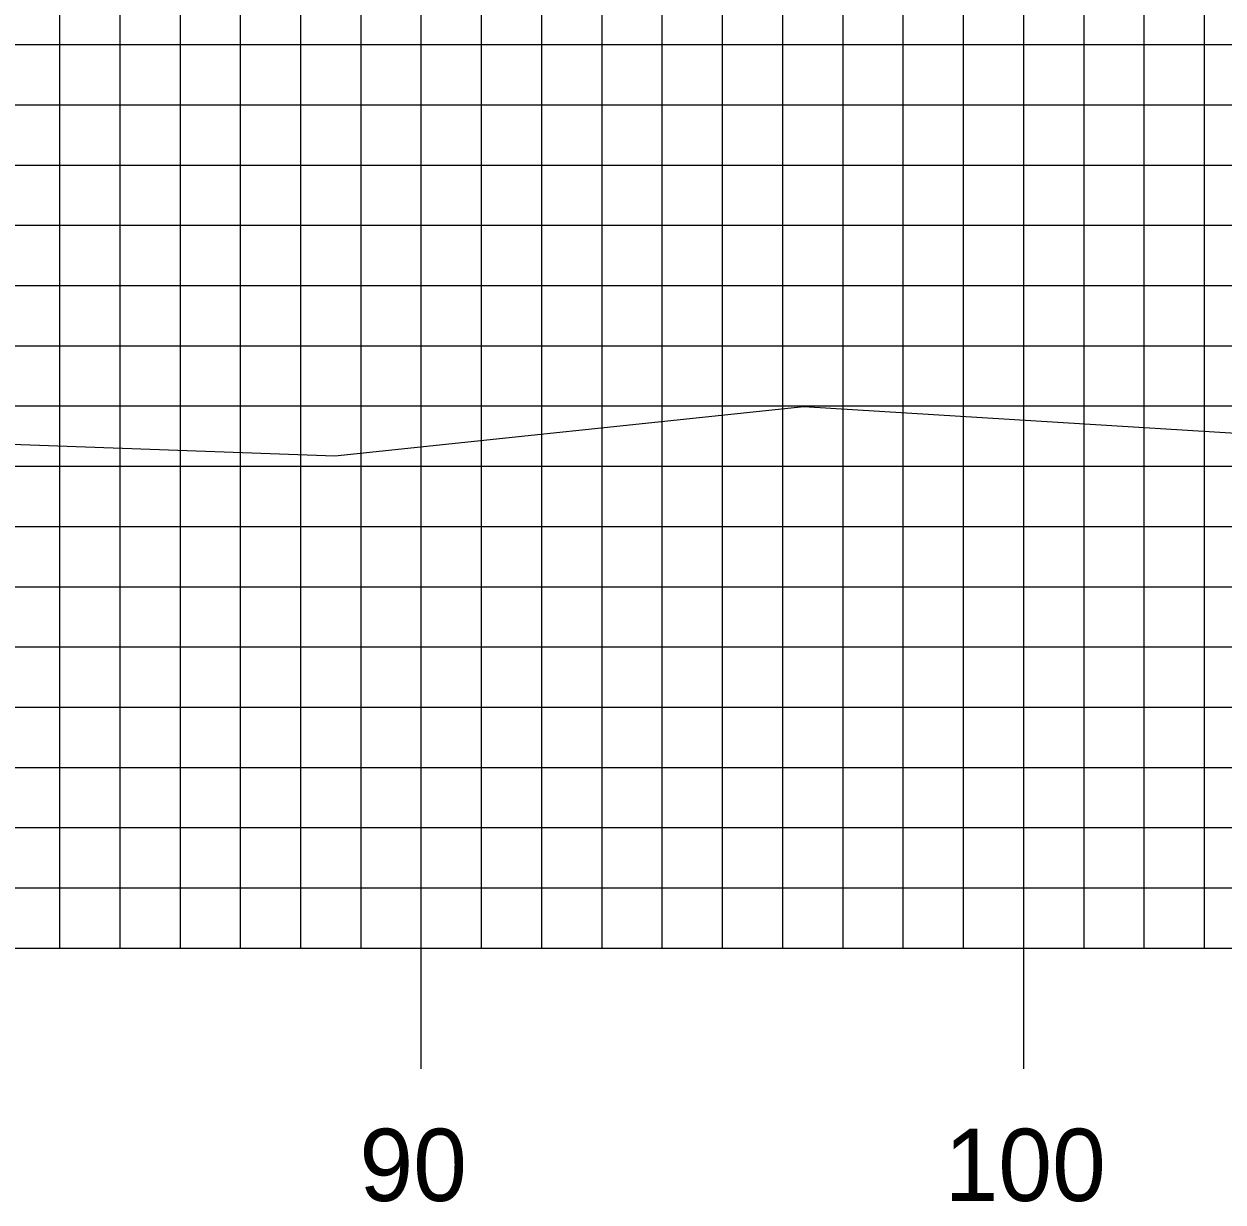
# Model space of a CAD drawing. Extents: x 1774777 to 1775120, y 442591 to 442811.
# Drawn here: x 1775026.09 to 1775045.99, y 442644.45 to 442664.01 of the extents above; entities that cross this region are included whole.
import ezdxf

# ---------------------------------------------------------------- set-up
doc = ezdxf.new("R2010")
doc.units = 0
for name, color, linetype in [('H_V ANNOTATION', 7, 'Continuous'), ('MAJOR', 7, 'Continuous'), ('MINOR', 7, 'Continuous'), ('S_Roadway_Centerline', 7, 'Continuous')]:
    doc.layers.add(name, color=color, linetype=linetype)

msp = doc.modelspace()

# ---------------------------------------------------------------- linework, layer by layer
at = {"layer": 'MAJOR'}
for p, q in [((1775032.685, 442648.665), (1775032.685, 442673.665)), ((1775042.685, 442648.665), (1775042.685, 442673.665)), ((1774802.685, 442663.665), (1775082.685, 442663.665)), ((1774802.685, 442658.665), (1775082.685, 442658.665)), ((1774802.685, 442653.665), (1775082.685, 442653.665)), ((1774802.685, 442648.665), (1775082.685, 442648.665)), ((1774802.685, 442648.665), (1775082.685, 442648.665)), ((1775032.685, 442646.661), (1775032.685, 442648.665)), ((1775042.685, 442646.661), (1775042.685, 442648.665))]:
    msp.add_line(p, q, dxfattribs=at)
at = {"layer": 'MINOR'}
for p, q in [((1775026.685, 442648.665), (1775026.685, 442673.665)), ((1775027.685, 442648.665), (1775027.685, 442673.665)), ((1775028.685, 442648.665), (1775028.685, 442673.665)), ((1775029.685, 442648.665), (1775029.685, 442673.665)), ((1775030.685, 442648.665), (1775030.685, 442673.665)), ((1775031.685, 442648.665), (1775031.685, 442673.665)), ((1775033.685, 442648.665), (1775033.685, 442673.665)), ((1775034.685, 442648.665), (1775034.685, 442673.665)), ((1775035.685, 442648.665), (1775035.685, 442673.665)), ((1775036.685, 442648.665), (1775036.685, 442673.665)), ((1775037.685, 442648.665), (1775037.685, 442673.665)), ((1775038.685, 442648.665), (1775038.685, 442673.665)), ((1775039.685, 442648.665), (1775039.685, 442673.665)), ((1775040.685, 442648.665), (1775040.685, 442673.665)), ((1775041.685, 442648.665), (1775041.685, 442673.665)), ((1775043.685, 442648.665), (1775043.685, 442673.665)), ((1775044.685, 442648.665), (1775044.685, 442673.665)), ((1775045.685, 442648.665), (1775045.685, 442673.665)), ((1774802.685, 442662.665), (1775082.685, 442662.665)), ((1774802.685, 442661.665), (1775082.685, 442661.665)), ((1774802.685, 442660.665), (1775082.685, 442660.665)), ((1774802.685, 442659.665), (1775082.685, 442659.665)), ((1774802.685, 442657.665), (1775082.685, 442657.665)), ((1774802.685, 442656.665), (1775082.685, 442656.665)), ((1774802.685, 442655.665), (1775082.685, 442655.665)), ((1774802.685, 442654.665), (1775082.685, 442654.665)), ((1774802.685, 442652.665), (1775082.685, 442652.665)), ((1774802.685, 442651.665), (1775082.685, 442651.665)), ((1774802.685, 442650.665), (1775082.685, 442650.665)), ((1774802.685, 442649.665), (1775082.685, 442649.665))]:
    msp.add_line(p, q, dxfattribs=at)
at = {"layer": 'S_Roadway_Centerline'}
msp.add_lwpolyline([(1775004.98, 442657.103), (1775007.238, 442657.307), (1775008.597, 442657.431), (1775009.789, 442657.447), (1775010.609, 442657.615), (1775010.886, 442657.635), (1775010.929, 442657.637), (1775012.239, 442657.681), (1775025.573, 442657.044), (1775031.251, 442656.835), (1775039.036, 442657.657), (1775050.067, 442656.974)], dxfattribs=at)

# ---------------------------------------------------------------- texts
at = {"layer": 'H_V ANNOTATION'}
for s, p in [('90', (1775031.657, 442644.465)), ('100', (1775041.369, 442644.465))]:
    msp.add_text(s, height=1.2, dxfattribs=at).set_placement(p)

doc.saveas('drawing.dxf')
